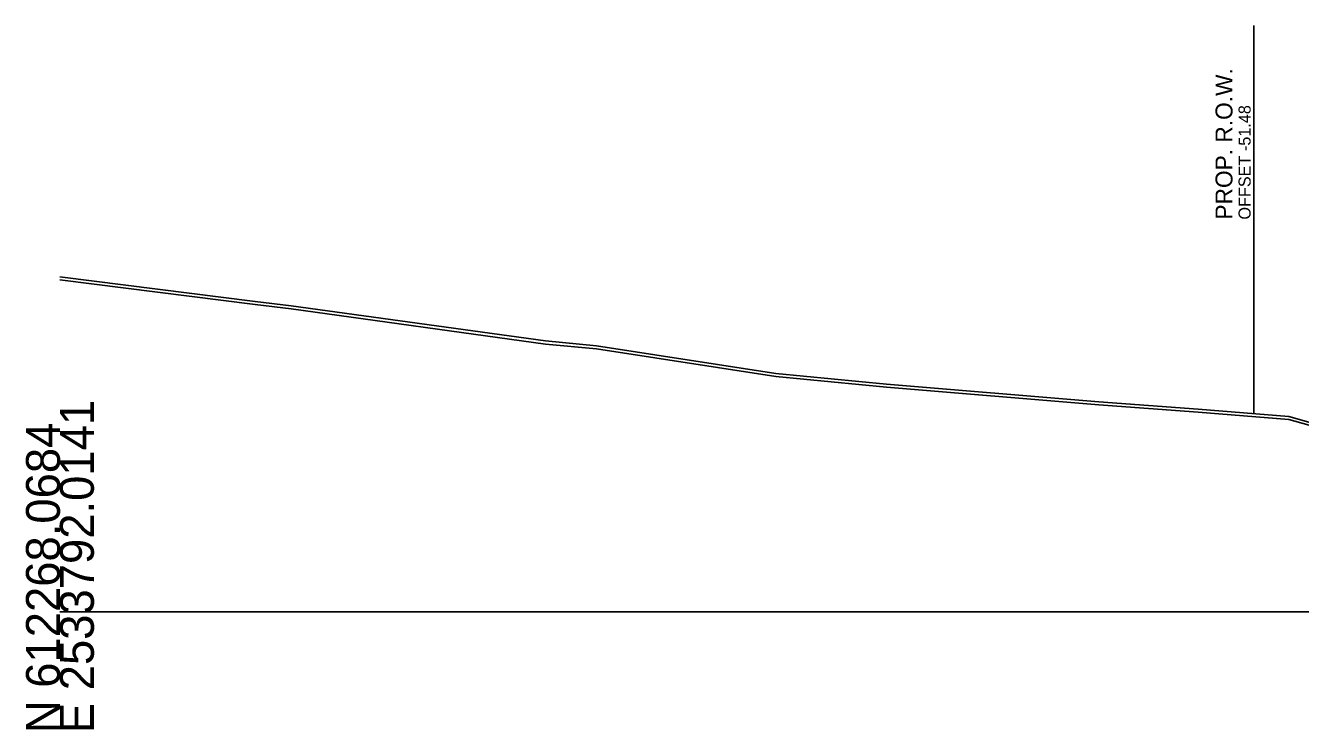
# Model space of a CAD drawing. Extents: x -120 to 2876, y -25 to 8560.
# Drawn here: x 1297.2 to 1402.4, y 990.3 to 1048.4 of the extents above; entities that cross this region are included whole.
import ezdxf

# ---------------------------------------------------------------- set-up
doc = ezdxf.new("R2010")
doc.units = 0
for name, color, linetype in [('DESIGN - ROW - Right-of-Way and Easement Labels', 7, 'Continuous'), ('DESIGN - ROW - Right-of-Way Linework', 7, 'Continuous'), ('DESIGN - SHEET - Light Grid', 7, 'Continuous'), ('SURVEY - GROUND - Bottom of Topsoil Layer', 7, 'Continuous'), ('SURVEY - GROUND - Top of Ground', 7, 'Continuous')]:
    doc.layers.add(name, color=color, linetype=linetype)

msp = doc.modelspace()

# ---------------------------------------------------------------- linework, layer by layer
at = {"layer": 'DESIGN - ROW - Right-of-Way Linework'}
msp.add_line((1398.52, 1016.35), (1398.52, 1048.35), dxfattribs=at)
at = {"layer": 'DESIGN - SHEET - Light Grid'}
msp.add_line((1300, 1000), (1450, 1000), dxfattribs=at)
at = {"layer": 'SURVEY - GROUND - Bottom of Topsoil Layer'}
for p, q in [((1300, 1027.38), (1316.1, 1025.36)), ((1316.1, 1025.36), (1319.08, 1024.99)), ((1319.08, 1024.99), (1340.07, 1022.09)), ((1340.07, 1022.09), (1344.27, 1021.69)), ((1344.27, 1021.69), (1359.08, 1019.4)), ((1359.08, 1019.4), (1368.22, 1018.54)), ((1368.22, 1018.54), (1385.73, 1017.08)), ((1385.73, 1017.08), (1393.95, 1016.47)), ((1393.95, 1016.47), (1401.41, 1015.87)), ((1401.41, 1015.87), (1411.11, 1013.12))]:
    msp.add_line(p, q, dxfattribs=at)
at = {"layer": 'SURVEY - GROUND - Top of Ground'}
msp.add_lwpolyline([(1300, 1027.63), (1316.1, 1025.61), (1319.08, 1025.24), (1340.07, 1022.34), (1344.27, 1021.94), (1359.08, 1019.65), (1368.22, 1018.79), (1385.73, 1017.33), (1393.95, 1016.72), (1401.41, 1016.12), (1411.11, 1013.37)], dxfattribs=at)

# ---------------------------------------------------------------- texts
at = {"layer": 'DESIGN - ROW - Right-of-Way and Easement Labels'}
for s, height, p in [('PROP. R.O.W.', 1.4, (1396.77, 1032.35)), ('OFFSET -51.48', 1, (1398.27, 1032.35))]:
    msp.add_text(s, height=height, rotation=90, dxfattribs=at).set_placement(p)
at = {"layer": 'DESIGN - SHEET - Light Grid'}
for s, p in [('E 2533792.0141', (1302.8, 990)), ('N 612268.0684', (1300, 990))]:
    msp.add_text(s, height=2.8, rotation=90, dxfattribs=at).set_placement(p)

doc.saveas('drawing.dxf')
